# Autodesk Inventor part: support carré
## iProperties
Created: 2002-05
Part Number: support carré
Material: Par défaut
Document SubType Name: Modélisation
Designer: REVEST Pierre
Control State: 0
Master: False
Checked Out: False
Shininess: 70.0
Length Units: 11269
Angle Units: 11279
Time Units: 11290
Mass Units: 11283
Length Display Precision: 3
Angle Display Precision: 2
Density: 0.0
Volumn: 0.0
Area: 0.0
PropertySet Name: Model Information
Author: REVEST Pierre
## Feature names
1. Extrusion1
2. Perçage1 [Hole]
3. Perçage2 [Hole]
